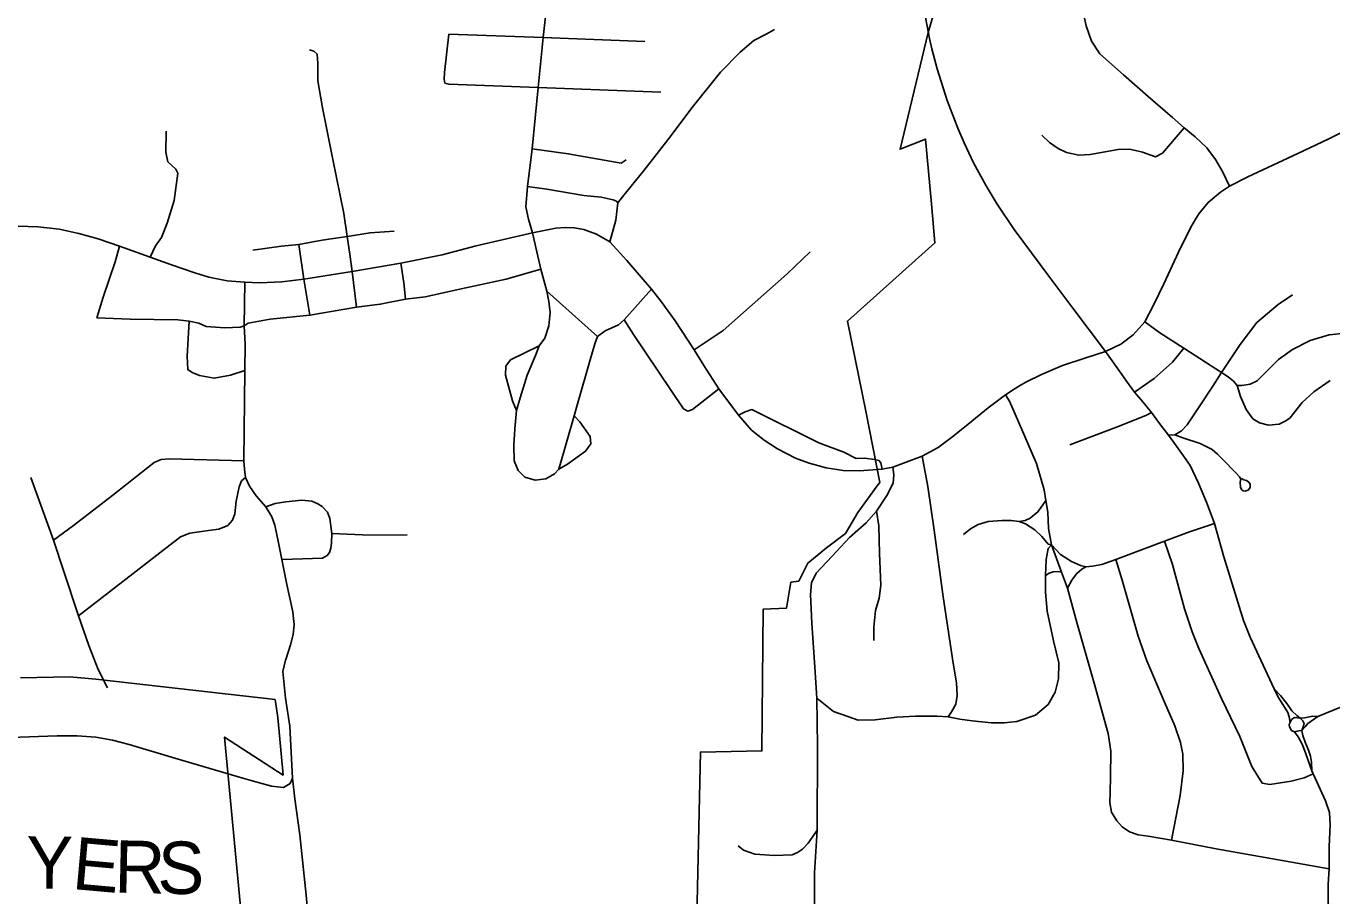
# Model space of a CAD drawing. Extents: x 2402298 to 2498138, y 789485 to 950881.
# Drawn here: x 2469210 to 2476688, y 866330 to 871312 of the extents above; entities that cross this region are included whole.
import ezdxf

# ---------------------------------------------------------------- set-up
doc = ezdxf.new("R2010")
doc.units = 0
for name, color, linetype in [('GM_X_City_Street', 7, 'Continuous'), ('GM_X_Corporation', 7, 'Continuous'), ('GM_X_County_Road', 7, 'Continuous'), ('GM_X_State_Route', 7, 'Continuous'), ('GM_X_Township_Road', 7, 'Continuous'), ('GM_X_Township_Road_Text', 7, 'Continuous')]:
    doc.layers.add(name, color=color, linetype=linetype)

msp = doc.modelspace()

# ---------------------------------------------------------------- linework, layer by layer
at = {"layer": 'GM_X_City_Street'}
msp.add_line((2472192.1, 869794.5), (2472481.1, 869533.9), dxfattribs=at)
for points in [[(2472110.5, 870127.3), (2472087.3, 870206.1), (2472072.5, 870275.8), (2472081.9, 870393.6), (2472107.8, 870608.2), (2472141.5, 870960.1), (2472171.7, 871247.1), (2472193.6, 871450.2), (2472217.3, 871670.1)], [(2476101.3, 870394.5), (2476061.8, 870479.9), (2476020.7, 870548.6), (2475972.2, 870613.9), (2475904.2, 870677.2), (2475841.5, 870729.7), (2475774.2, 870788.3), (2475634.8, 870909.6), (2475494, 871032.8), (2475358.6, 871153.4), (2475310.8, 871225.4), (2475281.2, 871313), (2475265.6, 871383.3), (2475251.6, 871446.3), (2475239.4, 871517.7)], [(2471606.8, 870984.5), (2471604.4, 871008.1), (2471606.4, 871047.1), (2471630.5, 871266.7)], [(2471630.5, 871266.7), (2472171.7, 871247.1), (2472752.7, 871224.7)], [(2472551.7, 870075.8), (2472587.2, 870201), (2472599.4, 870300.5), (2472626.1, 870334.3), (2472748.6, 870487.6), (2472898.9, 870677.2), (2473016.7, 870835.5), (2473187.2, 871047.4), (2473299.6, 871163.1), (2473376.8, 871230.2), (2473447.1, 871266.7), (2473496.6, 871292.4)], [(2471101.2, 869702.7), (2471076.1, 869906.6), (2471063.9, 870005.2), (2471048.4, 870106.1), (2471030.1, 870239.4), (2470965.8, 870548.1), (2470906.2, 870844.5), (2470879.8, 870998.2), (2470880.2, 871097.3), (2470877.1, 871151.8), (2470858.2, 871168.7), (2470832.4, 871175.5)], [(2471606.8, 870984.5), (2471629.8, 870978.7), (2472141.5, 870960.1), (2472845.1, 870934)], [(2469919.4, 869988.5), (2469951.2, 870052.6), (2469985, 870102), (2470016.8, 870183.2), (2470057.4, 870313.9), (2470077.7, 870469.5), (2470067.6, 870492.6), (2470020.9, 870535.2), (2470010.7, 870590), (2470011.4, 870710.5)], [(2475025.9, 870687.3), (2475070.4, 870646.2), (2475120.9, 870610.5), (2475168, 870587.6), (2475238.8, 870572.8), (2475302.7, 870576.9), (2475464.4, 870605.8), (2475530.4, 870607.2), (2475603.1, 870589.6), (2475678.5, 870562.7), (2475717.6, 870584.9), (2475841.5, 870729.7)], [(2472107.8, 870608.2), (2472314.4, 870580.7), (2472617.7, 870527.2), (2472646.1, 870545.5)], [(2472081.9, 870393.6), (2472192.6, 870377), (2472403.1, 870341.8), (2472503.3, 870331.6), (2472572.5, 870317.6), (2472589.9, 870309.5), (2472599.4, 870300.5)], [(2470508.4, 870028.7), (2470672.9, 870051.1), (2470771.7, 870061.9), (2470905, 870085.6), (2471048.4, 870106.1), (2471179.5, 870128.6), (2471317.6, 870137.4)], [(2472110.5, 870127.3), (2472134.6, 870019.9), (2472158.2, 869919.8), (2472192.1, 869794.5), (2472202.9, 869735), (2472210.4, 869672), (2472203.6, 869594.2), (2472179.9, 869523.8), (2472147.4, 869480.5), (2472127.8, 869425), (2472079.7, 869312.6), (2472039.8, 869183.3), (2472018.1, 869109.6), (2472008.7, 869005.3), (2472001.9, 868911.9), (2472003.9, 868822.6), (2472028.3, 868766.4), (2472066.2, 868728.5), (2472124.4, 868710.2), (2472185.3, 868718.3), (2472236.1, 868747.4), (2472261.1, 868774.5), (2472349.1, 869079.1), (2472365.4, 869140.7), (2472439.1, 869401.3), (2472466.9, 869492), (2472481.1, 869533.9), (2472525.8, 869566.4), (2472602.3, 869601), (2472634.1, 869628.7), (2472790.6, 869805)], [(2469614.4, 869640.7), (2469651.7, 869759.2), (2469719.3, 869960.9), (2469744.7, 870052.1)], [(2470835, 869655.5), (2470799.3, 869862.6), (2470771.7, 870061.9)], [(2473035.6, 869457.1), (2473202.1, 869569.1), (2473301.6, 869655.8), (2473569, 869892.7), (2473700.3, 870019.9)], [(2470458.3, 869594.9), (2470480.6, 869611.1), (2470607.9, 869632.8), (2470835, 869655.5), (2471101.2, 869702.7), (2471237.7, 869718.7), (2471382.6, 869747.5), (2471494.9, 869761), (2471728.1, 869812.5), (2471958.9, 869862.2), (2472158.2, 869919.8)], [(2471382.6, 869747.5), (2471372.7, 869840.9), (2471355.7, 869953.9)], [(2475751.8, 868968.7), (2475788.3, 868970.1), (2475826, 868993.7), (2475858.7, 869029), (2475928.4, 869130.7), (2476006.5, 869250.2), (2476056.4, 869327.4), (2476162.1, 869487.7), (2476258.8, 869613.6), (2476380, 869718), (2476462.8, 869772.5)], [(2469614.4, 869640.7), (2469805.6, 869632.9), (2470077.7, 869628.9), (2470143.1, 869622.4), (2470199.2, 869610.9), (2470241.6, 869591.7), (2470346.8, 869584.6), (2470435.3, 869586.7), (2470458.3, 869594.9)], [(2470143.1, 869622.4), (2470131.2, 869421.1), (2470135.6, 869344.9), (2470160.7, 869327.3), (2470202.6, 869310.4), (2470286.6, 869294.8), (2470380.6, 869312.4), (2470461.9, 869338.8)], [(2472634.1, 869628.7), (2472687.4, 869545.8), (2472975.2, 869119.7), (2472998.9, 869105.5), (2473025.3, 869116.3), (2473177.1, 869234.4)], [(2475616.5, 869617.9), (2475703.5, 869555.7), (2475840.4, 869467.2), (2476056.4, 869327.4), (2476094.4, 869302.8), (2476124.1, 869278.2), (2476144.9, 869252.6), (2476164.1, 869189.6), (2476196.5, 869115.2), (2476235.2, 869063), (2476273.9, 869038.8), (2476325.8, 869025.6), (2476386, 869032.4), (2476421.1, 869048.2), (2476446.7, 869066.4), (2476518, 869156), (2476584.7, 869216.9), (2476679, 869281.6)], [(2476144.9, 869252.6), (2476172.2, 869252.9), (2476220, 869260.4), (2476260.4, 869280.2), (2476326.4, 869346.2), (2476383, 869401.8), (2476462.2, 869460), (2476564.5, 869510.9), (2476671.6, 869543.6), (2476800.9, 869557.4), (2476892.2, 869557.4)], [(2472018.1, 869109.6), (2471994.4, 869165.1), (2471955.2, 869313.3), (2471957.9, 869364.1), (2471984.3, 869399.9), (2472147.4, 869480.5)], [(2475557.8, 869214.9), (2475669.5, 869294.4), (2475774.5, 869386.6), (2475840.4, 869467.2)], [(2476673, 866484.1), (2476025.6, 866600.1), (2475770.3, 866648.6), (2475636.3, 866671.5), (2475579.4, 866680.2), (2475529.2, 866697.7), (2475487.8, 866726.4), (2475455.8, 866759), (2475425.1, 866809.5), (2475416.7, 866862.1), (2475417.4, 866923.4), (2475420.1, 867011.6), (2475422.1, 867159.1), (2475407.3, 867260.8), (2475326.5, 867549), (2475226.8, 867896.5), (2475174.6, 868093.2), (2475140.3, 868185.1), (2475082.8, 868341.3), (2475065.2, 868434.8), (2475061.1, 868527.8), (2475050.3, 868595.5), (2475040.1, 868656.1), (2474995.5, 868806.3), (2474893.9, 869044.6), (2474842.5, 869163), (2474819.1, 869200.5)], [(2472261.1, 868774.5), (2472310.5, 868802.3), (2472412.7, 868877.4), (2472443.2, 868920), (2472439.8, 868960.6), (2472380.3, 869045.3), (2472349.1, 869079.1)], [(2473289.4, 869083.5), (2473327, 869102.1), (2473365.3, 869115.7), (2473750.5, 868924.6), (2473892.2, 868871), (2473963.9, 868835.8), (2474012.7, 868837.8), (2474067.5, 868829.7), (2474093.6, 868824.6), (2474105.1, 868809.7), (2474111.6, 868774.5)], [(2475186.9, 868913.5), (2475454.3, 869015.5), (2475622, 869081.9), (2475654.1, 869098.2)], [(2475788.3, 868970.1), (2475835.2, 868953.8), (2475934.1, 868921.3), (2476003.2, 868886.9), (2476032.6, 868860.8), (2476061.1, 868830.7), (2476138.2, 868753.7), (2476159.1, 868730.2), (2476165.8, 868717.4), (2476162.8, 868700.2), (2476164.8, 868671.6), (2476170.2, 868658.1), (2476180, 868650.3), (2476193.8, 868649), (2476210.9, 868655.1), (2476219.7, 868669.5), (2476219.7, 868687.4), (2476211.9, 868698.8), (2476198.5, 868708.6), (2476183, 868713.6), (2476169.9, 868720.7)], [(2469367.1, 868367.7), (2469481.8, 868451.5), (2469706.8, 868626.1), (2469871, 868755.7), (2469943.7, 868812.2), (2469983, 868829.4), (2470029.9, 868833.7), (2470456.6, 868822.8)], [(2474490.5, 867355.5), (2474509.5, 867384.9), (2474534.5, 867428.2), (2474541.3, 867477.6), (2474537.2, 867550.8), (2474519.6, 867662.4), (2474462.1, 868042.2), (2474409.3, 868423.9), (2474374.8, 868675.7), (2474340.8, 868849)], [(2473702, 865498.2), (2473704.7, 865632.9), (2473720.9, 866022.1), (2473725.7, 866080.3), (2473725.7, 866228.5), (2473724.3, 866462.7), (2473739.9, 866705.7), (2473741.2, 867188.3), (2473737.9, 867463.1), (2473727, 867640.4), (2473709.4, 867892.9), (2473702, 868056), (2473707.4, 868123), (2473735.2, 868179.2), (2473825.9, 868276), (2473925.4, 868382.9), (2474020.1, 868467.6), (2474080.4, 868533.2), (2474139.9, 868623.2), (2474175.1, 868694.3), (2474179.2, 868741), (2474173.2, 868786)], [(2469676.4, 867522.2), (2469621.5, 867626.4), (2469569.4, 867764.5), (2469510.5, 867935), (2469423.9, 868193.6), (2469367.1, 868367.7), (2469237.1, 868725.6)], [(2469510.5, 867935), (2470093.3, 868385.8), (2470147.5, 868407.5), (2470253.7, 868423.1), (2470314, 868430.5), (2470364.7, 868452.2), (2470391.1, 868481.3), (2470404.7, 868517.8), (2470412.8, 868590.9), (2470429.7, 868672.8), (2470443.2, 868706.7), (2470466.9, 868725.6)], [(2470674.7, 868255.9), (2470734.3, 868257.9), (2470906.9, 868264), (2470933.3, 868280.2), (2470946.2, 868296.5), (2470953.9, 868321.2), (2470957.7, 868350.3), (2470960, 868406.5), (2470948.2, 868491.8), (2470935.7, 868527), (2470905.9, 868559.8), (2470879.5, 868576.4), (2470846.3, 868589.9), (2470788.4, 868595.7), (2470697.1, 868586.9), (2470635.5, 868577), (2470582.8, 868558.7)], [(2474064.8, 867792.4), (2474065.5, 867869.6), (2474074.9, 867965), (2474095.9, 868036.1), (2474105.4, 868109.8), (2474098, 868291.9), (2474092.5, 868450.3), (2474080.4, 868533.2)], [(2474577.9, 868400.1), (2474618, 868431.8), (2474662.4, 868456.7), (2474718.7, 868474.9), (2474798.8, 868480), (2474850.7, 868479.3), (2474897.1, 868473.6), (2474930.8, 868480.3), (2474959.4, 868493.1), (2475004.6, 868528.8), (2475032.8, 868570.5), (2475050.3, 868595.5)], [(2475082.8, 868341.3), (2475063.8, 868344.6), (2475027.5, 868388), (2474986.7, 868425.7), (2474932.8, 868460.8), (2474897.1, 868473.6)], [(2475082.8, 868341.3), (2475132.9, 868284.5), (2475196.2, 868245.4), (2475248.7, 868222.8), (2475279, 868215.1), (2475316.9, 868219.4), (2475370.6, 868227.9), (2475451.4, 868256.2), (2475730.2, 868361.6), (2475872.7, 868414.8), (2476015.7, 868462.7)], [(2470960, 868406.5), (2471137, 868398.3), (2471392.2, 868397)], [(2473737.9, 867463.1), (2473777.1, 867432.6), (2473834, 867386.6), (2473915.1, 867357.5), (2473974.8, 867336.5), (2474071.6, 867338.6), (2474195.4, 867352.8), (2474303.7, 867358.9), (2474426.9, 867358.9), (2474490.5, 867355.5), (2474556.9, 867342.6), (2474628.6, 867332.5), (2474737.6, 867321), (2474812, 867320.3), (2474884.5, 867328.4), (2474990.1, 867365), (2475063.2, 867426.5), (2475103.8, 867496.3), (2475122.7, 867572.4), (2475124.7, 867664.5), (2475094.3, 867791.7), (2475057.1, 867960.2), (2475048.3, 868069.2), (2475046.9, 868164.7), (2475051.6, 868257.4), (2475063.2, 868319.7), (2475082.8, 868341.3)], [(2476289.6, 866975.9), (2476230.3, 867070.2), (2476160.3, 867242.6), (2476055.9, 867460.1), (2475926.6, 867746.4), (2475886.8, 867842), (2475843, 867974.7), (2475774.3, 868227.2), (2475730.2, 868361.6)], [(2475770.3, 866648.6), (2475818.1, 866905.2), (2475836.3, 867045.9), (2475835, 867140.9), (2475820.8, 867208.2), (2475788.5, 867303.2), (2475728.6, 867439.2), (2475628.9, 867677), (2475577.7, 867817.7), (2475540, 867951.8), (2475486.1, 868137.7), (2475451.4, 868256.2)], [(2475046.9, 868164.7), (2475067.9, 868178.1), (2475091.4, 868186.1), (2475118.4, 868187.8), (2475140.3, 868185.1)], [(2475174.6, 868093.2), (2475199.5, 868139), (2475225.5, 868174), (2475256.4, 868200.6), (2475279, 868215.1)], [(2476289.6, 866975.9), (2476332.7, 866967.8), (2476454.6, 866986.7), (2476529.3, 867006.2), (2476580.1, 867029.3)], [(2473287.8, 866617), (2473317.5, 866592), (2473383.2, 866569.6), (2473496.2, 866561.5), (2473596.4, 866565.6), (2473627.9, 866578.8), (2473655.3, 866596.7), (2473688.5, 866632.6), (2473714.8, 866669.8), (2473739.9, 866705.7)]]:
    msp.add_lwpolyline(points, dxfattribs=at)
at = {"layer": 'GM_X_Corporation'}
for points in [[(2473036.1, 865518.5), (2473071.7, 867153.5), (2473423.8, 867160.2), (2473431.7, 867972.4), (2473563.7, 867977.7), (2473590, 868126.7), (2473634.7, 868131.9), (2473686.5, 868236.5), (2473792.7, 868323.6), (2473901.4, 868405.1), (2473973.1, 868525.3), (2474084.5, 868678), (2474098.2, 868698.2), (2474020.3, 869097.7), (2473913.2, 869622.4), (2474414.5, 870069.9), (2474395, 870293.9), (2474360.9, 870664.5), (2474215, 870606.7), (2474376, 871275.2), (2474415.9, 871412.9)], [(2474415.9, 871412.9), (2474376, 871275.2), (2474215, 870606.7), (2474360.9, 870664.5), (2474395, 870293.9), (2474414.5, 870069.9), (2473913.2, 869622.4), (2474020.3, 869097.7), (2474098.2, 868698.2), (2474084.5, 868678), (2473973.1, 868525.3), (2473901.4, 868405.1), (2473792.7, 868323.6), (2473686.5, 868236.5), (2473634.7, 868131.9), (2473590, 868126.7), (2473563.7, 867977.7), (2473431.7, 867972.4), (2473423.8, 867160.2), (2473071.7, 867153.5), (2473036.1, 865518.5)], [(2470469, 865923.7), (2470346.5, 867239.3), (2470681, 867021.8), (2470650.9, 867350.9), (2470635.3, 867454.7), (2469609.2, 867571.2), (2469460.8, 867584.1), (2469177.1, 867578.6)]]:
    msp.add_lwpolyline(points, dxfattribs=at)
at = {"layer": 'GM_X_County_Road'}
for p, q in [((2475390.5, 869448.7), (2475198.4, 869704.2)), ((2475481.8, 869321.2), (2475390.5, 869448.7)), ((2475512.2, 869278.7), (2475481.8, 869321.2)), ((2470735.7, 867003.8), (2470727.4, 867152.7))]:
    msp.add_line(p, q, dxfattribs=at)
for points in [[(2474384.3, 871240.4), (2474377, 871272.4), (2474353.1, 871400.8), (2474339.3, 871495.7), (2474338.7, 871501)], [(2475198.4, 869704.2), (2475067.2, 869878.8), (2474868.7, 870146.9), (2474770.7, 870291.2), (2474708.1, 870397.8), (2474636, 870529.6), (2474582, 870643.6), (2474545.4, 870727.2), (2474485, 870885.6), (2474426.9, 871067.9), (2474397.6, 871181.8), (2474384.3, 871240.4)], [(2470698.4, 867690.1), (2470724.1, 867768.2), (2470739.4, 867827.1), (2470745.1, 867885), (2470739.2, 867935.6), (2470736.7, 867956.7), (2470703.2, 868114.1), (2470674.7, 868255.9), (2470655.4, 868352), (2470633.1, 868453.9), (2470617.6, 868501.6), (2470582.8, 868558.7), (2470526.8, 868621.7), (2470489.3, 868677.2), (2470466.9, 868725.6), (2470459.5, 868775), (2470456.6, 868822.8), (2470461.9, 869338.8), (2470463.2, 869490.5), (2470458.3, 869594.9), (2470462.3, 869845.5)], [(2476358, 867515.8), (2476219.3, 867811.4), (2476182.5, 867906.6), (2476069, 868271.2), (2476015.7, 868462.7), (2475970, 868584.2), (2475924.9, 868694.3), (2475876, 868795.3), (2475836, 868852.2), (2475798.6, 868905.1), (2475767.6, 868947.5), (2475751.8, 868968.7), (2475701.6, 869036.4), (2475654.1, 869098.2), (2475604.6, 869160.3), (2475557.8, 869214.9), (2475512.2, 869278.7)], [(2470727.4, 867152.7), (2470719.1, 867301.7), (2470694.3, 867462.8), (2470687.3, 867538.1), (2470680.1, 867615), (2470695.4, 867680.9), (2470698.4, 867690.1)], [(2476573.1, 867045.5), (2476571.1, 867094.2), (2476565.6, 867131), (2476554.5, 867165), (2476535.7, 867209.5), (2476521.1, 867248.4), (2476516.3, 867277.5), (2476523.2, 867297.7), (2476528.8, 867317.1), (2476522.5, 867332.4), (2476506.5, 867348.4), (2476486.4, 867362.3), (2476459.3, 867390), (2476429.5, 867432.4), (2476394, 867476.8), (2476358, 867515.8)], [(2476358, 867515.8), (2476380.1, 867468.5), (2476420.4, 867405.3), (2476436.4, 867380.3), (2476443.3, 867354.6), (2476449, 867322.7), (2476443.3, 867310.9), (2476444.7, 867298.4), (2476455.8, 867278.2), (2476473.4, 867269.9), (2476494.7, 867241.4), (2476519, 867194.9), (2476538.5, 867144.2), (2476573.1, 867045.5)], [(2476607.5, 867358.3), (2476826.8, 867447.4)], [(2476607.5, 867358.3), (2476579.5, 867359.5), (2476531.5, 867350.5), (2476506.5, 867348.4), (2476473.2, 867351.1), (2476456.5, 867340), (2476449, 867322.7)], [(2476473.4, 867269.9), (2476498.2, 867274.8), (2476516.3, 867277.5), (2476534.3, 867299.1), (2476551, 867317.1), (2476607.5, 867358.3)], [(2468849.7, 867228.4), (2469387.6, 867246.5), (2469501.3, 867246.5), (2469609.3, 867238.9), (2469703.9, 867221.2), (2469800.4, 867196.4), (2470062.2, 867119.4), (2470450, 867004)], [(2476823.8, 865786), (2476724.6, 866074.8), (2476667.2, 866286.8), (2476666.7, 866396.7), (2476673, 866484.1), (2476673.3, 866612.1), (2476678.5, 866736.8), (2476674.6, 866807.6), (2476650.9, 866874.9), (2476580.1, 867029.3), (2476573.1, 867045.5)], [(2470450, 867004), (2470490.8, 866991.9), (2470614.5, 866957.9), (2470682.9, 866951.2), (2470721.1, 866973.7), (2470735.7, 867003.8)]]:
    msp.add_lwpolyline(points, dxfattribs=at)
at = {"layer": 'GM_X_State_Route'}
for points in [[(2476836.8, 870749), (2476669.7, 870666.6), (2476493.1, 870582.5), (2476321.2, 870501.4), (2476206.5, 870447.9), (2476101.3, 870394.5), (2476050.2, 870360.2), (2475979.3, 870301.9), (2475925.9, 870237), (2475899.2, 870192.6)], [(2475899.2, 870192.6), (2475877.8, 870157.1), (2475809.3, 870016.5), (2475726.4, 869836.3), (2475667.5, 869717.3), (2475616.5, 869617.9), (2475550.3, 869544.2), (2475487, 869496)], [(2474121.8, 868776.4), (2474111.6, 868774.5), (2473980.9, 868764.6), (2473889.6, 868767.2), (2473791.6, 868781.1), (2473694.3, 868808.8), (2473616.2, 868837.6), (2473512.2, 868889.9), (2473435.9, 868940.4), (2473364.4, 868996.9), (2473289.4, 869083.5), (2473177.1, 869234.4), (2473091.8, 869367.8), (2473035.6, 869457.1), (2472927.3, 869623), (2472847.5, 869735.3), (2472790.6, 869805), (2472650.5, 869970.2), (2472551.7, 870075.8), (2472476.5, 870120.4), (2472404.6, 870146.7), (2472349.3, 870157), (2472299.2, 870159), (2472243.7, 870155), (2472110.5, 870127.3), (2471786.8, 870052.8), (2471591.9, 870002), (2471355.7, 869953.9), (2471076.1, 869906.6), (2470799.3, 869862.6), (2470674.1, 869846.3), (2470548.7, 869841.6), (2470462.3, 869845.5), (2470362, 869852.4), (2470256.4, 869874.7), (2470176.6, 869898.4), (2470041.9, 869943.8), (2469919.4, 869988.5), (2469744.7, 870052.1), (2469621.5, 870092.7), (2469511.9, 870124.5), (2469399.5, 870148.2), (2469276.3, 870161.7), (2469164, 870165.8)], [(2475390.5, 869448.7), (2475278.7, 869412.7), (2475145.3, 869367.6), (2475025.2, 869317.1), (2474935, 869273.3), (2474908.5, 869257.3)], [(2475487, 869496), (2475482.4, 869492.6), (2475390.5, 869448.7)], [(2474908.5, 869257.3), (2474873.2, 869236), (2474819.1, 869200.5), (2474718.7, 869126), (2474605.8, 869032.3), (2474517.5, 868961.4), (2474432.1, 868898.9), (2474340.8, 868849), (2474173.2, 868786), (2474121.8, 868776.4)]]:
    msp.add_lwpolyline(points, dxfattribs=at)
at = {"layer": 'GM_X_Township_Road'}
msp.add_line((2470823.3, 866230.8), (2470812.6, 866333.7), dxfattribs=at)
msp.add_lwpolyline([(2470812.6, 866333.7), (2470776.5, 866678.7), (2470749.1, 866885.4), (2470735.7, 867003.8)], dxfattribs=at)

# ---------------------------------------------------------------- texts
at = {"layer": 'GM_X_Township_Road_Text'}
for s, rotation, p in [('Y', 359.46086, (2469209.6, 866372.2)), ('E', 354.87192, (2469467.3, 866370.1)), ('R', 358.78595, (2469713.1, 866348.8)), ('S', 358.94903, (2469960.4, 866343.5))]:
    msp.add_text(s, height=300, rotation=rotation, dxfattribs=at).set_placement(p)

doc.saveas('drawing.dxf')
